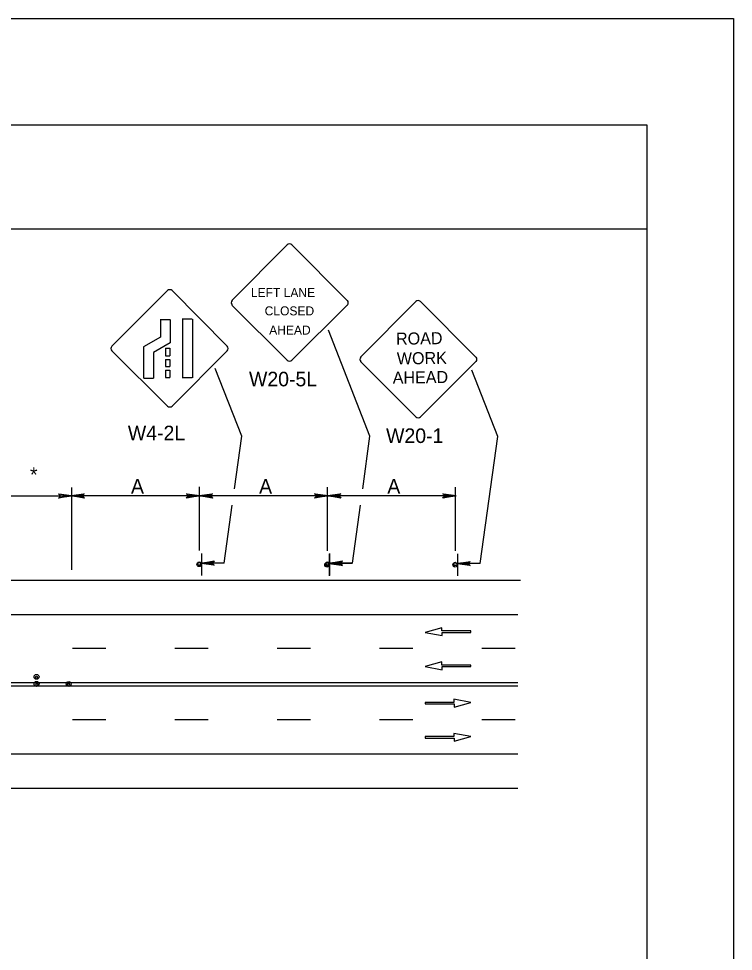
# Model space of a CAD drawing. Extents: x -14145 to -13662, y 30244 to 30661.
# Drawn here: x -13835.49 to -13825.17, y 30409.86 to 30423.31 of the extents above; entities that cross this region are included whole.
import ezdxf

# ---------------------------------------------------------------- set-up
doc = ezdxf.new("R2010")
doc.units = 0
for name, color, linetype in [('1', 7, 'Continuous'), ('10', 7, 'Continuous'), ('2', 7, 'Continuous'), ('61', 7, 'Continuous')]:
    doc.layers.add(name, color=color, linetype=linetype)

msp = doc.modelspace()

# ---------------------------------------------------------------- linework, layer by layer
at = {"layer": '1'}
for p, q in [((-13831.614, 30420.046), (-13832.409, 30419.243)), ((-13830.745, 30419.243), (-13831.547, 30420.046)), ((-13834.142, 30418.582), (-13833.339, 30419.385)), ((-13833.272, 30419.385), (-13832.477, 30418.582)), ((-13829.757, 30419.23), (-13830.552, 30418.427)), ((-13828.888, 30418.427), (-13829.69, 30419.23)), ((-13832.409, 30419.177), (-13831.614, 30418.382)), ((-13831.547, 30418.382), (-13830.745, 30419.177)), ((-13833.445, 30418.971), (-13833.304, 30418.971)), ((-13833.441, 30418.969), (-13833.441, 30418.714)), ((-13833.3, 30418.969), (-13833.3, 30418.631)), ((-13833.125, 30418.976), (-13832.984, 30418.976)), ((-13833.121, 30418.974), (-13833.121, 30418.127)), ((-13832.98, 30418.974), (-13832.98, 30418.127)), ((-13830.417, 30417.288), (-13831.016, 30418.816)), ((-13833.441, 30418.714), (-13833.683, 30418.575)), ((-13833.683, 30418.575), (-13833.683, 30418.122)), ((-13833.3, 30418.631), (-13833.542, 30418.492)), ((-13833.37, 30418.555), (-13833.305, 30418.555)), ((-13833.37, 30418.555), (-13833.37, 30418.447)), ((-13833.305, 30418.555), (-13833.305, 30418.447)), ((-13833.339, 30417.721), (-13834.141, 30418.516)), ((-13833.542, 30418.492), (-13833.542, 30418.122)), ((-13833.37, 30418.447), (-13833.305, 30418.447)), ((-13832.477, 30418.516), (-13833.272, 30417.721)), ((-13833.37, 30418.394), (-13833.305, 30418.394)), ((-13833.37, 30418.394), (-13833.37, 30418.289)), ((-13833.37, 30418.289), (-13833.305, 30418.289)), ((-13833.305, 30418.394), (-13833.305, 30418.289)), ((-13830.552, 30418.361), (-13829.757, 30417.566)), ((-13829.69, 30417.566), (-13828.888, 30418.361)), ((-13833.37, 30418.237), (-13833.305, 30418.237)), ((-13833.37, 30418.237), (-13833.37, 30418.132)), ((-13833.305, 30418.237), (-13833.305, 30418.132)), ((-13832.267, 30417.288), (-13832.65, 30418.264)), ((-13828.573, 30417.282), (-13828.948, 30418.237)), ((-13833.682, 30418.122), (-13833.541, 30418.122)), ((-13833.37, 30418.132), (-13833.305, 30418.132)), ((-13833.125, 30418.13), (-13832.984, 30418.13)), ((-13832.372, 30416.525), (-13832.267, 30417.288)), ((-13830.522, 30416.525), (-13830.417, 30417.288)), ((-13828.825, 30415.451), (-13828.573, 30417.282)), ((-13834.725, 30416.546), (-13834.725, 30415.36)), ((-13832.875, 30415.638), (-13832.875, 30416.558)), ((-13831.031, 30415.632), (-13831.031, 30416.552)), ((-13829.181, 30415.632), (-13829.181, 30416.552)), ((-13837.042, 30416.424), (-13834.725, 30416.424)), ((-13832.875, 30416.424), (-13834.725, 30416.424)), ((-13831.025, 30416.424), (-13832.875, 30416.424)), ((-13829.175, 30416.424), (-13831.025, 30416.424)), ((-13832.519, 30415.457), (-13832.404, 30416.292)), ((-13830.669, 30415.457), (-13830.554, 30416.292)), ((-13832.85, 30415.595), (-13832.85, 30415.277)), ((-13831.006, 30415.589), (-13831.006, 30415.271)), ((-13831, 30415.595), (-13831, 30415.277)), ((-13829.156, 30415.589), (-13829.156, 30415.271)), ((-13832.52, 30415.457), (-13832.85, 30415.457)), ((-13830.67, 30415.457), (-13831, 30415.457)), ((-13830.676, 30415.451), (-13831.006, 30415.451)), ((-13828.826, 30415.451), (-13829.156, 30415.451)), ((-13855.332, 30415.209), (-13828.244, 30415.209)), ((-13855.372, 30414.717), (-13828.284, 30414.717)), ((-13829.379, 30414.522), (-13829.62, 30414.456)), ((-13829.379, 30414.477), (-13829.379, 30414.522)), ((-13829.62, 30414.456), (-13829.376, 30414.41)), ((-13828.963, 30414.477), (-13829.379, 30414.477)), ((-13829.376, 30414.41), (-13829.376, 30414.455)), ((-13829.376, 30414.455), (-13828.963, 30414.455)), ((-13828.963, 30414.455), (-13828.963, 30414.477)), ((-13834.228, 30414.225), (-13834.708, 30414.225)), ((-13832.752, 30414.225), (-13833.232, 30414.225)), ((-13831.276, 30414.225), (-13831.756, 30414.225)), ((-13829.8, 30414.225), (-13830.28, 30414.225)), ((-13828.324, 30414.225), (-13828.804, 30414.225)), ((-13829.379, 30414.03), (-13829.62, 30413.964)), ((-13829.379, 30413.985), (-13829.379, 30414.03)), ((-13828.963, 30413.985), (-13829.379, 30413.985)), ((-13828.963, 30413.963), (-13828.963, 30413.985)), ((-13829.62, 30413.964), (-13829.376, 30413.918)), ((-13829.376, 30413.918), (-13829.376, 30413.963)), ((-13829.376, 30413.963), (-13828.963, 30413.963)), ((-13855.372, 30413.733), (-13828.284, 30413.733)), ((-13855.372, 30413.688), (-13828.284, 30413.688)), ((-13829.206, 30413.447), (-13829.62, 30413.447)), ((-13829.62, 30413.447), (-13829.62, 30413.425)), ((-13828.963, 30413.446), (-13829.206, 30413.492)), ((-13829.206, 30413.492), (-13829.206, 30413.447)), ((-13829.204, 30413.379), (-13828.963, 30413.446)), ((-13829.62, 30413.425), (-13829.204, 30413.425)), ((-13829.204, 30413.425), (-13829.204, 30413.379)), ((-13834.228, 30413.196), (-13834.708, 30413.196)), ((-13832.752, 30413.196), (-13833.232, 30413.196)), ((-13831.276, 30413.196), (-13831.756, 30413.196)), ((-13829.8, 30413.196), (-13830.28, 30413.196)), ((-13828.324, 30413.196), (-13828.804, 30413.196)), ((-13829.206, 30412.955), (-13829.62, 30412.955)), ((-13829.62, 30412.955), (-13829.62, 30412.933)), ((-13829.62, 30412.933), (-13829.204, 30412.933)), ((-13828.963, 30412.954), (-13829.206, 30413)), ((-13829.206, 30413), (-13829.206, 30412.955)), ((-13829.204, 30412.887), (-13828.963, 30412.954)), ((-13829.204, 30412.933), (-13829.204, 30412.887)), ((-13855.372, 30412.704), (-13828.284, 30412.704)), ((-13855.372, 30412.212), (-13828.284, 30412.212))]:
    msp.add_line(p, q, dxfattribs=at)
for points in [[(-13834.905, 30416.448), (-13834.893, 30416.43), (-13834.725, 30416.424), (-13834.905, 30416.448), (-13834.911, 30416.454), (-13834.725, 30416.424), (-13834.893, 30416.418), (-13834.899, 30416.4), (-13834.725, 30416.424), (-13834.911, 30416.394), (-13834.899, 30416.4)], [(-13834.545, 30416.406), (-13834.551, 30416.418), (-13834.725, 30416.424), (-13834.545, 30416.406), (-13834.539, 30416.394), (-13834.725, 30416.424), (-13834.557, 30416.436), (-13834.551, 30416.448), (-13834.725, 30416.424), (-13834.539, 30416.454), (-13834.551, 30416.448)], [(-13833.055, 30416.448), (-13833.049, 30416.436), (-13832.875, 30416.424), (-13833.055, 30416.448), (-13833.067, 30416.454), (-13832.875, 30416.424), (-13833.049, 30416.418), (-13833.055, 30416.406), (-13832.875, 30416.424), (-13833.067, 30416.394), (-13833.055, 30416.406)], [(-13832.695, 30416.406), (-13832.701, 30416.418), (-13832.875, 30416.424), (-13832.695, 30416.406), (-13832.689, 30416.394), (-13832.875, 30416.424), (-13832.707, 30416.436), (-13832.701, 30416.448), (-13832.875, 30416.424), (-13832.689, 30416.454), (-13832.701, 30416.448)], [(-13831.205, 30416.448), (-13831.199, 30416.436), (-13831.025, 30416.424), (-13831.205, 30416.448), (-13831.217, 30416.454), (-13831.025, 30416.424), (-13831.199, 30416.418), (-13831.205, 30416.406), (-13831.025, 30416.424), (-13831.217, 30416.394), (-13831.205, 30416.406)], [(-13830.845, 30416.406), (-13830.851, 30416.418), (-13831.025, 30416.424), (-13830.845, 30416.406), (-13830.839, 30416.394), (-13831.025, 30416.424), (-13830.857, 30416.436), (-13830.851, 30416.448), (-13831.025, 30416.424), (-13830.839, 30416.454), (-13830.851, 30416.448)], [(-13829.355, 30416.448), (-13829.349, 30416.436), (-13829.175, 30416.424), (-13829.355, 30416.448), (-13829.367, 30416.454), (-13829.175, 30416.424), (-13829.349, 30416.418), (-13829.355, 30416.406), (-13829.175, 30416.424), (-13829.367, 30416.394), (-13829.355, 30416.406)], [(-13832.676, 30415.433), (-13832.682, 30415.445), (-13832.85, 30415.457), (-13832.676, 30415.433), (-13832.664, 30415.427), (-13832.85, 30415.457), (-13832.682, 30415.463), (-13832.676, 30415.475), (-13832.85, 30415.457), (-13832.664, 30415.487), (-13832.676, 30415.475)], [(-13830.832, 30415.427), (-13830.838, 30415.439), (-13831.006, 30415.451), (-13830.832, 30415.427), (-13830.82, 30415.421), (-13831.006, 30415.451), (-13830.838, 30415.457), (-13830.832, 30415.469), (-13831.006, 30415.451), (-13830.82, 30415.481), (-13830.832, 30415.469)], [(-13830.826, 30415.433), (-13830.832, 30415.445), (-13831, 30415.457), (-13830.826, 30415.433), (-13830.814, 30415.427), (-13831, 30415.457), (-13830.832, 30415.463), (-13830.826, 30415.475), (-13831, 30415.457), (-13830.814, 30415.487), (-13830.826, 30415.475)], [(-13828.982, 30415.427), (-13828.988, 30415.439), (-13829.156, 30415.451), (-13828.982, 30415.427), (-13828.97, 30415.421), (-13829.156, 30415.451), (-13828.988, 30415.457), (-13828.982, 30415.469), (-13829.156, 30415.451), (-13828.97, 30415.481), (-13828.982, 30415.469)]]:
    msp.add_lwpolyline(points, dxfattribs=at)
for centre, radius in [((-13832.882, 30415.438), 0.0325), ((-13831.038, 30415.432), 0.0325), ((-13831.032, 30415.438), 0.0325), ((-13829.188, 30415.432), 0.0325), ((-13835.228, 30413.816), 0.0354), ((-13835.228, 30413.714), 0.0354), ((-13835.231, 30413.813), 0.0143), ((-13835.225, 30413.711), 0.0143), ((-13834.765, 30413.713), 0.0354), ((-13834.768, 30413.71), 0.0143)]:
    msp.add_circle(centre, radius, dxfattribs=at)
for centre, radius, start, end in [((-13831.579, 30420.013), 0.0465, 45, 135), ((-13833.305, 30419.352), 0.0465, 45, 135), ((-13832.374, 30419.211), 0.0465, 135, 225), ((-13830.776, 30419.21), 0.0465, 315, 45), ((-13829.723, 30419.197), 0.0465, 45, 135), ((-13834.108, 30418.549), 0.0465, 135, 225), ((-13832.51, 30418.55), 0.0465, 315, 45), ((-13830.518, 30418.394), 0.0465, 135, 225), ((-13828.92, 30418.394), 0.0465, 315, 45), ((-13831.579, 30418.415), 0.0465, 225, 315), ((-13833.305, 30417.754), 0.0465, 225, 315), ((-13829.722, 30417.599), 0.0465, 225, 315), ((-13832.882, 30415.449), 0.0214, 355.7499, 350.479), ((-13831.038, 30415.443), 0.0214, 355.7499, 350.479), ((-13831.032, 30415.449), 0.0214, 355.7499, 350.479), ((-13829.188, 30415.443), 0.0214, 355.7499, 350.479)]:
    msp.add_arc(centre, radius, start, end, dxfattribs=at)
at = {"layer": '10'}
for p, q in [((-13857.874, 30421.777), (-13826.422, 30421.777)), ((-13826.422, 30421.777), (-13826.422, 30399.207)), ((-13857.874, 30420.277), (-13826.422, 30420.277))]:
    msp.add_line(p, q, dxfattribs=at)
at = {"layer": '61'}
msp.add_lwpolyline([(-13858.174, 30423.307), (-13825.174, 30423.307), (-13825.174, 30397.807), (-13858.174, 30397.807)], close=True, dxfattribs=at)

# ---------------------------------------------------------------- texts
at = {"layer": '1'}
for s, p in [('LEFT LANE', (-13832.136, 30419.291)), ('CLOSED', (-13831.937, 30419.028)), ('AHEAD', (-13831.872, 30418.751))]:
    msp.add_text(s, height=0.13, dxfattribs=at).set_placement(p)
for s, height, rotation, p in [('ROAD', 0.1735, 0.7566, (-13830.04, 30418.605)), ('WORK', 0.1733, 0.7588, (-13830.028, 30418.32)), ('AHEAD', 0.1735, 0.7481, (-13830.088, 30418.043))]:
    msp.add_text(s, height=height, rotation=rotation, dxfattribs=at).set_placement(p)
at = {"layer": '2'}
for s, p in [('W20-5L', (-13832.163, 30418.005)), ('W4-2L', (-13833.911, 30417.227)), ('W20-1', (-13830.185, 30417.188)), ('*', (-13835.323, 30416.626)), ('A', (-13833.866, 30416.458)), ('A', (-13832.017, 30416.458)), ('A', (-13830.167, 30416.458))]:
    msp.add_text(s, height=0.21, dxfattribs=at).set_placement(p)

doc.saveas('drawing.dxf')
